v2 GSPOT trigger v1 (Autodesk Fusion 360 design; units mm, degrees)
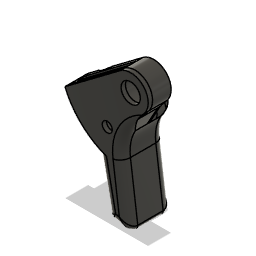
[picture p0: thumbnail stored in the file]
description: Part Number
part number: GSPOT glock frt
base_feature "Base Feature1"
base_feature "Base Feature1" bodies "Frame"
base_feature "Base Feature1"
base_feature "Base Feature1"
base_feature "Base Feature1" bodies "Baseplate - Angled", "Locking Plate", "Magazine", "9mm Follower"
align "Align1"
align "Align2"
extrude "Extrude1" new body of existing geometry blind 15.5
move "Move1"
combine "Combine1"
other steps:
create_component "CreateComponent1"
create_component "CreateComponent1"
create_component "CreateComponent2"
create_component "CreateComponent3"
create_component "CreateComponent1"
named bodies: "Baseplate - Angled", "Locking Plate", "Magazine", "9mm Follower", "Frame"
